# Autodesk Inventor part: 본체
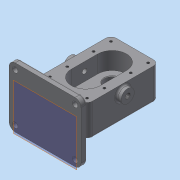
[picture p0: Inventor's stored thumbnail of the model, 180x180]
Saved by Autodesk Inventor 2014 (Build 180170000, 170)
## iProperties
Created: 2026-10
Part Number: 본체
Material: 일반
Document SubType Name: Modeling
Designer: dg
Density: 1 g/cm^3
Appearance: 기본값
Author: dg
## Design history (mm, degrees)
sketch "스케치1"
  geometry: L1 (-40, 60)-(40, 60); L2 (40, 60)-(40, -60); L3 (40, -60)-(-40, -60); L4 (-40, -60)-(-40, 60); 3 further points
  constraints: 8 end point, 2 midpoint, 2 parallel, 1 horizontal, 1 horizontal alignment, 1 perpendicular, 1 vertical alignment
  dimensions: "d0" = 80 distance of L1.start L1.end; "d1" = 120 distance of L3.end L1.start
extrude "돌출1" new body sketch "스케치1" stored distance "d2" = 53; taper "d3" = 0 deg
sketch "스케치2"
  geometry: L1 (-40, 60)-(-40, -60) reference; L2 (0, 22)-(0, -22); L3 (-24, 22)-(-24, -22); L4 (24, -22)-(24, 22); A1 r 24 centre (0, 22) between (24, 22) and (-24, 22); A2 r 24 centre (0, -22) between (-24, -22) and (24, -22); 2 further points
  constraints: 8 end point, 4 point on circle, 4 tangent, 2 centre point, 2 coincident, 2 parallel, 1 midpoint
  dimensions: "d4" = 44 distance of L2.end L2.start; "d6" = 48 distance between parallel lines of L4 L3
extrude "돌출2" cut sketch "스케치2" distance "d7" = 29; taper "d8" = 0 deg
fillet "모깎기1" dims "d9" = 9
sketch "스케치5"
  geometry: C1 r 19 at (0, 22); 1 further point
  constraints: 1 centre point, 1 vertical alignment
  dimensions: "d13" = 22 distance of point (0, 0) C1.centre; "d14" = 38 diameter of C1
extrude "돌출3" join sketch "스케치5" distance "d15" = 17; taper "d16" = 0 deg
sketch "스케치6"
  geometry: L1 (22, -2.623)-(22, -43.5); L2 (3, -43.5)-(41, -43.5) reference; L3 (22, -2.5)-(46, -2.5) reference; L4 (34.5, -2.5)-(34.5, -17.5); L5 (34.5, -17.5)-(30.5, -17.5); L6 (30.5, -17.5)-(30.5, -36.2); L7 (30.5, -36.2)-(36, -36.2); L8 (36, -36.2)-(36, -42.8); L9 (36, -42.8)-(36.404, -43.5); L10 (-22, -2.623)-(-22, -17.5); L11 (-22, -17.5)-(-9.5, -17.5); L12 (-9.5, -17.5)-(-9.5, -2.5); L13 (-22, -2.5)-(22, -2.5) reference; L14 (34.5, -2.5)-(22, -2.5); L15 (36.404, -43.5)-(22, -43.5); L16 (-9.5, -2.5)-(-22, -2.5); L17 (22, -2.5)-(22, -43.5); L18 (-22, -2.5)-(-22, -17.5); 1 further point
  constraints: 30 end point, 5 parallel, 3 collinear, 3 point on line, 2 perpendicular, 1 horizontal, 1 midpoint, 1 vertical
  dimensions: "d17" = 22 distance from line of point (0, 0) L1; "d18" = 7.3 distance from line of L9.end L7; "d19" = 30 deg angle of L8 L9; "d20" = 15 distance of L4.start L4.end; "d21" = 25 diameter of L4 L1; "d22" = 17 diameter of L6 L1; "d25" = 0.7 vertical distance of L8.end L9.end; "d26" = 22 distance from line of L10 point (0, 0); "d27" = 25 diameter of L12 L10; "d28" = 15 distance of L11.end L12.end; "d115" = 28 diameter of L8 L1
revolve "회전1" stored, may be unused: angle "d29" = 90 deg
revolve "회전2" stored, may be unused: angle "d30" = 90 deg
node "작업 평면1"
sketch "스케치7"
  geometry: L1 (-60, 56.5)-(60, 56.5); L2 (60, 56.5)-(60, -43.5); L3 (-60, -43.5)-(-60, 56.5); L4 (-19, -43.5)-(19, -43.5) reference; L5 (-60, -43.5)-(60, -43.5); 3 further points
  constraints: 8 end point, 3 midpoint, 2 parallel, 1 collinear, 1 horizontal, 1 perpendicular, 1 vertical alignment
  dimensions: "d34" = 100 distance of L3.start L1.start; "d35" = 120 distance between parallel lines of L2 L3
extrude "돌출4" join sketch "스케치7" distance "d36" = 10; taper "d37" = 0 deg
sketch "스케치8"
  geometry: L1 (-80, -43.5)-(-80, 56.5) reference; L2 (-80, 26.5)-(-46, 6.87); L3 (-46, -6.87)-(-80, -26.5); L4 (-46, 6.87)-(-46, -6.87); L5 (-46, 26.5)-(-46, -2.5) reference; 2 further points
  constraints: 6 end point, 3 point on line, 1 midpoint, 1 parallel
  dimensions: "d38" = 17 distance of L1.start L3.end; "d39" = 53 distance of L3.end L2.start; "d40" = 60 deg angle of L1 L2; "d41" = 60 deg angle of L1 L3
extrude "돌출5" join sketch "스케치8" stored distance "d42" = 48; taper "d43" = 0 deg
fillet "모깎기2" dims "d49" = 10
sketch "스케치10"
  geometry: A1 r 9 centre (31, 51) between (40, 51) and (31, 60) reference; A2 r 9 centre (-31, 51) between (-31, 60) and (-40, 51) reference; 5 further points
  constraints: 2 coincident, 2 vertical alignment, 1 horizontal alignment
  dimensions: "d50" = 29 distance of point (-31, 22) point (-31, 51)
hole "구멍1" sketch "스케치10" at (-31, 51), (-31, 22), (31, 51), (31, 22) diameter "d51" = 4.134; stored, may be unused: countersink angle "d55" = 82 deg, drill point angle "d57" = 118 deg; dims "d52" = 10, "d53" = 3.023, "d54" = 2, "d56" = 12
node "작업 평면2"
sketch "스케치11"
  geometry: L1 (-40, 51)-(-40, -51) reference; L2 (40, -51)-(40, 51) reference; L3 (-40, 0)-(-48, 0); L4 (40, 0)-(48, 0); L5 (-48, 0)-(-48, 11); L6 (-48, 11)-(-40, 11); L7 (48, 0)-(48, 11); L8 (48, 11)-(40, 11); 1 further point
  constraints: 12 end point, 5 perpendicular, 2 midpoint, 2 point on line, 1 collinear, 1 horizontal alignment
  dimensions: "d59" = 22 diameter of L6 L3; "d60" = 48 distance from line of point (0, 0) L5; "d61" = 96 distance between parallel lines of L7 L5
revolve "회전4" sketch "스케치11" stored, may be unused: angle "d62" = 90 deg
hole "구멍2" diameter "d65" = 8; stored, may be unused: countersink angle "d71" = 90 deg, drill point angle "d73" = 0 deg; dims "d63" = 10, "d64" = 10, "d66" = 9, "d67" = 0.62479, "d68" = 7.985, "d69" = 4, "d70" = 2, "d72" = 8
hole "구멍3" diameter "d76" = 8; stored, may be unused: countersink angle "d82" = 90 deg, drill point angle "d84" = 0 deg; dims "d74" = 10, "d75" = 10, "d77" = 9, "d78" = 0.62479, "d79" = 7.985, "d80" = 4, "d81" = 2, "d83" = 8
sketch "스케치13"
  geometry: L1 (-60, 33.5)-(-60, -46.5) reference; L2 (-50, -56.5)-(50, -56.5) reference; L3 (50, 43.5)-(-50, 43.5) reference; L4 (31, 26.5)-(31, -26.5) reference; L5 (-31, 26.5)-(31, 26.5) reference; L6 (-31, -26.5)-(-31, 26.5) reference; L7 (31, -26.5)-(-31, -26.5) reference; C1 r 4.5 at (-50, -46.5); C2 r 4.5 at (50, -46.5); C3 r 4.5 at (-50, 33.5); C4 r 4.5 at (50, 33.5); A1 r 10 centre (-50, -46.5) between (-60, -46.5) and (-50, -56.5) reference; 1 further point
  constraints: 4 centre point, 3 equal radius, 2 horizontal alignment, 2 vertical alignment
  dimensions: "d88" = 9 diameter of C3; "d89" = 10 distance from line of L3 C3.centre; "d90" = 10 distance from line of L2 C1.centre; "d94" = 10 distance from line of L1 C1.centre; "d95" = 100 distance of C2.centre A1.centre
extrude "돌출6" cut sketch "스케치13" stored distance "d96" = 10; taper "d97" = 0 deg
fillet "모깎기3" dims "d98" = 3
fillet "모깎기4" dims "d99" = 3
fillet "모깎기5" dims "d100" = 3
fillet "모깎기6" dims "d101" = 3
fillet "모깎기7" dims "d102" = 3
fillet "모깎기8" dims "d103" = 3
fillet "모깎기9" dims "d104" = 3
chamfer "모따기1" distance "d105" = 1; stored, may be unused: second distance "d106" = 2, angle "d107" = 45 deg
chamfer "모따기2" distance "d108" = 1; stored, may be unused: second distance "d109" = 2, angle "d110" = 45 deg
fillet "모깎기10" dims "d111" = 0.5
sketch "스케치14"
  geometry: L1 (-50, -56.5)-(50, -56.5) reference; 2 further points
  constraints: 1 vertical alignment, 1 other
  dimensions: "d112" = 10 distance from line of L1 point (0, -46.5)
feature "엠보싱1" sketch "스케치14" dims "d113" = 0.4, "d114" = 0
sketch "스케치15"
  geometry: 1 further point
node "솔리드1"
mirror "대칭1"
node "투영된 루프1"
other parameters: "d58" = 12.5
